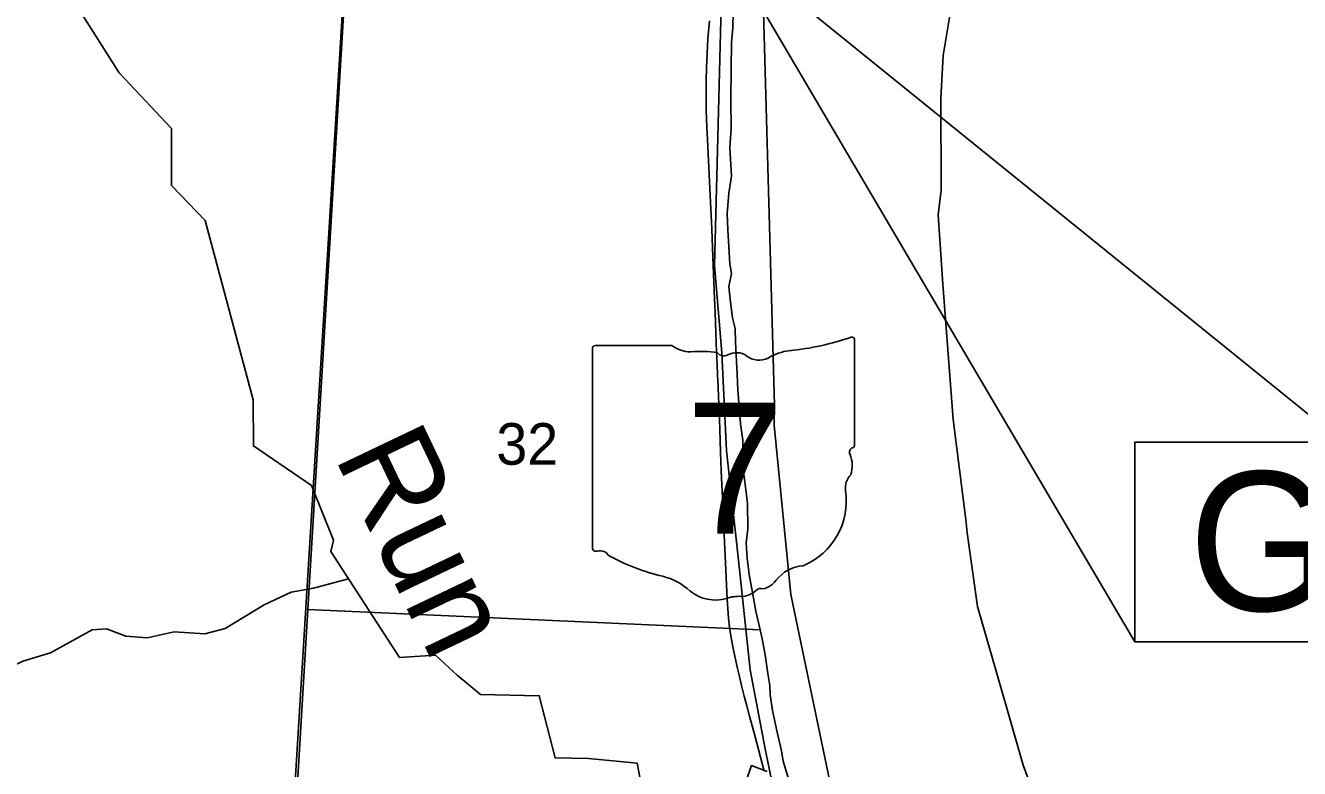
# Model space of a CAD drawing. Extents: x 0 to 34, y 0 to 22.
# Drawn here: x 5.797 to 7.078, y 17.002 to 17.749 of the extents above; entities that cross this region are included whole.
import ezdxf

# ---------------------------------------------------------------- set-up
doc = ezdxf.new("R2010")
doc.units = 0
for name, color, linetype in [('Default', 7, 'Continuous'), ('GM_X_Major_River', 7, 'Continuous'), ('GM_X_Minor_River', 7, 'Continuous'), ('GM_X_Minor_River_Text', 7, 'Continuous'), ('GM_X_Section', 7, 'Continuous'), ('GM_X_Section_Text', 7, 'Continuous'), ('GM_X_State_Location', 7, 'Continuous'), ('GM_X_State_Route', 7, 'Continuous'), ('GM_X_State_Shield', 7, 'Continuous'), ('SH_Text', 7, 'Continuous')]:
    doc.layers.add(name, color=color, linetype=linetype)

msp = doc.modelspace()

# ---------------------------------------------------------------- linework, layer by layer
at = {"layer": 'Default'}
for points in [[(3.9292, 16.0191), (4.6644, 15.9921), (4.9525, 15.9829), (5.4606, 15.953), (5.4699, 15.9536), (5.4787, 15.9537), (5.4884, 15.9532), (5.5007, 15.9519), (5.5038, 15.9516), (5.5088, 15.951), (5.5156, 15.9503), (5.5249, 15.9499), (5.5387, 15.9494), (5.5476, 15.9495), (5.5597, 15.9496), (5.5657, 15.9498), (5.5704, 15.951), (5.5736, 15.9525), (5.5744, 15.953), (5.6773, 15.9486), (6.0035, 15.9327), (6.0487, 16.67), (6.0603, 16.8624), (6.127, 17.9511)], [(6.127, 17.9511), (6.0603, 16.8624), (6.0487, 16.67), (6.5224, 16.6444), (6.7022, 16.6326), (6.841, 16.6271), (6.7947, 16.6724), (6.7412, 16.7413), (6.6572, 16.8728), (6.6092, 16.9726), (6.5665, 17.1768), (6.5499, 17.3472), (6.5502, 17.3673), (6.5359, 17.8831)]]:
    msp.add_lwpolyline(points, dxfattribs=at)
at = {"layer": 'GM_X_Major_River'}
for points in [[(6.7178, 17.5835), (6.7174, 17.6757), (6.7199, 17.719), (6.7384, 17.8299)], [(6.4976, 17.8073), (6.4924, 17.6107), (6.4898, 17.5078), (6.4973, 17.4197), (6.5019, 17.3214), (6.514, 17.2114), (6.5258, 17.1009), (6.5409, 17.0216), (6.5482, 16.9852), (6.5697, 16.9098), (6.5979, 16.8416), (6.625, 16.7771), (6.67, 16.6892), (6.7102, 16.6378), (6.7228, 16.6264), (6.7671, 16.5894), (6.807, 16.5512), (6.9003, 16.4768), (6.9575, 16.4357), (7.0708, 16.372), (7.0939, 16.3645)], [(7.1477, 16.6232), (6.9976, 16.724), (6.932, 16.778), (6.87, 16.8537), (6.8514, 16.884), (6.8293, 16.9268), (6.8003, 17.0049), (6.7845, 17.0602), (6.7543, 17.1645), (6.7441, 17.2389), (6.7426, 17.2521), (6.7301, 17.3527), (6.7197, 17.489), (6.7149, 17.5588), (6.7178, 17.5835)]]:
    msp.add_lwpolyline(points, dxfattribs=at)
at = {"layer": 'GM_X_Minor_River'}
for points in [[(6.4235, 16.9471), (6.4121, 17.007), (6.363, 17.0119), (6.3296, 17.0124), (6.3136, 17.0748), (6.2544, 17.0762), (6.231, 17.0957), (6.2091, 17.1157), (6.173, 17.1134), (6.104, 17.2199), (6.1066, 17.2313), (6.0846, 17.2865), (6.026, 17.3262), (6.0257, 17.3725), (5.9774, 17.5528), (5.9436, 17.5881), (5.9436, 17.6455), (5.8908, 17.7015), (5.8497, 17.7665)], [(6.1218, 17.1925), (6.0866, 17.1832), (6.0639, 17.179), (6.037, 17.1664), (5.9975, 17.1424), (5.9771, 17.1371), (5.9464, 17.1393), (5.9191, 17.1332), (5.8978, 17.1347), (5.8781, 17.1423), (5.8637, 17.1411), (5.822, 17.1179), (5.794, 17.1095), (5.7758, 17.1011), (5.7477, 17.0969), (5.7197, 17.1011), (5.6825, 17.112), (5.6711, 17.1139), (5.659, 17.12), (5.642, 17.1508), (5.6219, 17.1626), (5.6026, 17.1876), (5.587, 17.2074), (5.5776, 17.2275)], [(6.5429, 16.9987), (6.5271, 17.0046), (6.515, 16.9704)]]:
    msp.add_lwpolyline(points, dxfattribs=at)
at = {"layer": 'GM_X_Section'}
for points in [[(5.0782, 18.0036), (6.1294, 17.9583), (6.1188, 17.7931), (6.0808, 17.1618), (6.0674, 16.9363), (5.0081, 16.9831)], [(6.5357, 17.1413), (6.5377, 17.1323), (6.5407, 17.116), (6.5435, 17.0974), (6.5454, 17.0853), (6.5458, 17.0762), (6.5481, 17.0599), (6.5528, 17.0383), (6.5574, 17.0194), (6.5589, 17.0092), (6.5631, 16.9956), (6.5673, 16.9831), (6.5746, 16.9657), (6.5788, 16.9498), (6.5846, 16.932), (6.5892, 16.9187), (6.5918, 16.9087), (6.0674, 16.9363), (6.0808, 17.1618)]]:
    msp.add_lwpolyline(points, close=True, dxfattribs=at)
msp.add_lwpolyline([(6.5086, 17.7626), (6.5082, 17.7467), (6.5068, 17.7319), (6.5065, 17.7058), (6.5062, 17.6736), (6.5067, 17.6455), (6.5053, 17.6262), (6.5069, 17.5978), (6.5043, 17.5804), (6.5025, 17.5599), (6.5033, 17.5436), (6.5053, 17.5095), (6.5068, 17.4997), (6.5042, 17.4864), (6.5058, 17.4709), (6.5081, 17.455), (6.5108, 17.4444), (6.5109, 17.4307), (6.5125, 17.3985), (6.5133, 17.3822), (6.5161, 17.3485), (6.5184, 17.3319), (6.5181, 17.308), (6.5212, 17.2849), (6.5232, 17.2682), (6.5233, 17.2428), (6.5218, 17.2284), (6.5226, 17.2133), (6.5246, 17.197), (6.528, 17.1788), (6.5315, 17.1599), (6.5357, 17.1413), (6.0808, 17.1618), (6.1188, 17.7931)], dxfattribs=at)
at = {"layer": 'GM_X_State_Route'}
msp.add_lwpolyline([(6.5399, 16.999), (6.5303, 17.035), (6.5277, 17.0446), (6.5251, 17.0542), (6.5223, 17.0649), (6.5198, 17.0745), (6.5171, 17.0853), (6.5146, 17.0955), (6.513, 17.1022), (6.5112, 17.11), (6.5082, 17.124), (6.5063, 17.135), (6.5049, 17.1437), (6.5039, 17.153), (6.5027, 17.1722), (6.5008, 17.2082), (6.5001, 17.2224), (6.4994, 17.2441), (6.4986, 17.2615), (6.4976, 17.2807), (6.4965, 17.3012), (6.4959, 17.3198), (6.4955, 17.3316), (6.4945, 17.3639), (6.494, 17.3745), (6.4935, 17.3862), (6.493, 17.3974), (6.4925, 17.408), (6.492, 17.4216), (6.4917, 17.4297), (6.4913, 17.4402), (6.4904, 17.4607), (6.4897, 17.4743), (6.4882, 17.5159), (6.4871, 17.5444), (6.4855, 17.578), (6.4849, 17.5922), (6.4828, 17.6344), (6.4823, 17.6468), (6.4816, 17.6636), (6.4815, 17.6761), (6.4816, 17.6846), (6.4816, 17.6941), (6.4818, 17.7065), (6.482, 17.714), (6.4833, 17.7357), (6.4847, 17.7537)], dxfattribs=at)
at = {"layer": 'GM_X_State_Shield'}
for p, q in [((6.6308, 17.3276), (6.6308, 17.4322)), ((6.3671, 17.4238), (6.3671, 17.2237)), ((6.4469, 17.4273), (6.3697, 17.4273)), ((6.6308, 17.3276), (6.6308, 17.3276))]:
    msp.add_line(p, q, dxfattribs=at)
for centre, radius, start, end in [((6.5369, 17.7001), 0.2796, 275.8445, 288.9065), ((6.6279, 17.4327), 0.00294, 351.8621, 97.738), ((6.3702, 17.4243), 0.00305, 98.1301, 188.1301), ((6.4653, 17.4505), 0.0296, 231.6195, 271.1119), ((6.4752, 17.3149), 0.1064, 80.4867, 94.9883), ((6.4993, 17.4253), 0.00855, 219.7921, 297.1024), ((6.5119, 17.4022), 0.0178, 54.4667, 119.1411), ((6.5725, 17.3662), 0.0563, 97.3462, 120.7689), ((6.5348, 17.4339), 0.0214, 233.8562, 294.8282), ((6.6301, 17.3199), 0.00454, 107.944, 210.337), ((6.6012, 17.3066), 0.0273, 340.033, 23.6496), ((6.6277, 17.3271), 0.00314, 289.6038, 7.7341), ((6.6413, 17.2837), 0.0198, 136.8065, 186.9296), ((6.5525, 17.2704), 0.0699, 292.3089, 8.9858), ((6.3702, 17.2233), 0.00308, 171.9584, 258.3066), ((6.3707, 17.2438), 0.0235, 267.339, 280.6039), ((6.3755, 17.2122), 0.00848, 29.7484, 93.2717), ((6.4825, 17.392), 0.2019, 240.4129, 257.1985), ((6.582, 17.1675), 0.0383, 94.4031, 142.5768), ((6.4223, 17.1338), 0.0632, 47.1842, 75.836), ((6.5335, 17.2043), 0.0226, 282.8732, 323.2771), ((6.4907, 17.2112), 0.0401, 230.7004, 286.2918), ((6.5138, 17.142), 0.0329, 85.6951, 111.2099), ((6.5167, 17.1962), 0.0214, 268.777, 315.5493), ((6.5361, 17.1768), 0.00601, 65.7517, 132.6484)]:
    msp.add_arc(centre, radius, start, end, dxfattribs=at)
at = {"layer": 'SH_Text'}
msp.add_lwpolyline([(7.0892, 16.4411), (6.9521, 16.5634), (6.8963, 16.5881), (6.841, 16.6271), (6.7947, 16.6724), (6.7412, 16.7413), (6.6572, 16.8728), (6.6092, 16.9726), (6.5665, 17.1768), (6.5499, 17.3472), (6.5502, 17.3673), (6.5359, 17.8831)], dxfattribs=at)
for points in [[(6.9128, 17.129), (6.4968, 17.8355), (7.122, 17.3299), (6.9128, 17.3299)], [(6.9128, 17.3299), (8.145, 17.3299), (8.145, 17.129), (6.9128, 17.129)]]:
    msp.add_lwpolyline(points, close=True, dxfattribs=at)

# ---------------------------------------------------------------- texts
at = {"layer": 'GM_X_Minor_River_Text'}
msp.add_text('Run', height=0.0947, rotation=295.5123, dxfattribs=at).set_placement((6.1068, 17.316))
at = {"layer": 'GM_X_Section_Text'}
msp.add_text('32', height=0.04186, rotation=0, dxfattribs=at).set_placement((6.2704, 17.3073))
at = {"layer": 'GM_X_State_Location'}
for s in ['s', 'r']:
    msp.add_text(s, height=0.000189, dxfattribs=at).set_placement((6.496, 17.3105))
msp.add_text('7', height=0.000189, rotation=0, dxfattribs=at).set_placement((6.4675, 17.2967))
at = {"layer": 'GM_X_State_Shield'}
msp.add_text('7', height=0.1318, dxfattribs=at).set_placement((6.4612, 17.2378))
at = {"layer": 'SH_Text'}
msp.add_text('GAL-7-19.94', height=0.14, dxfattribs=at).set_placement((6.9669, 17.1603))

doc.saveas('drawing.dxf')
